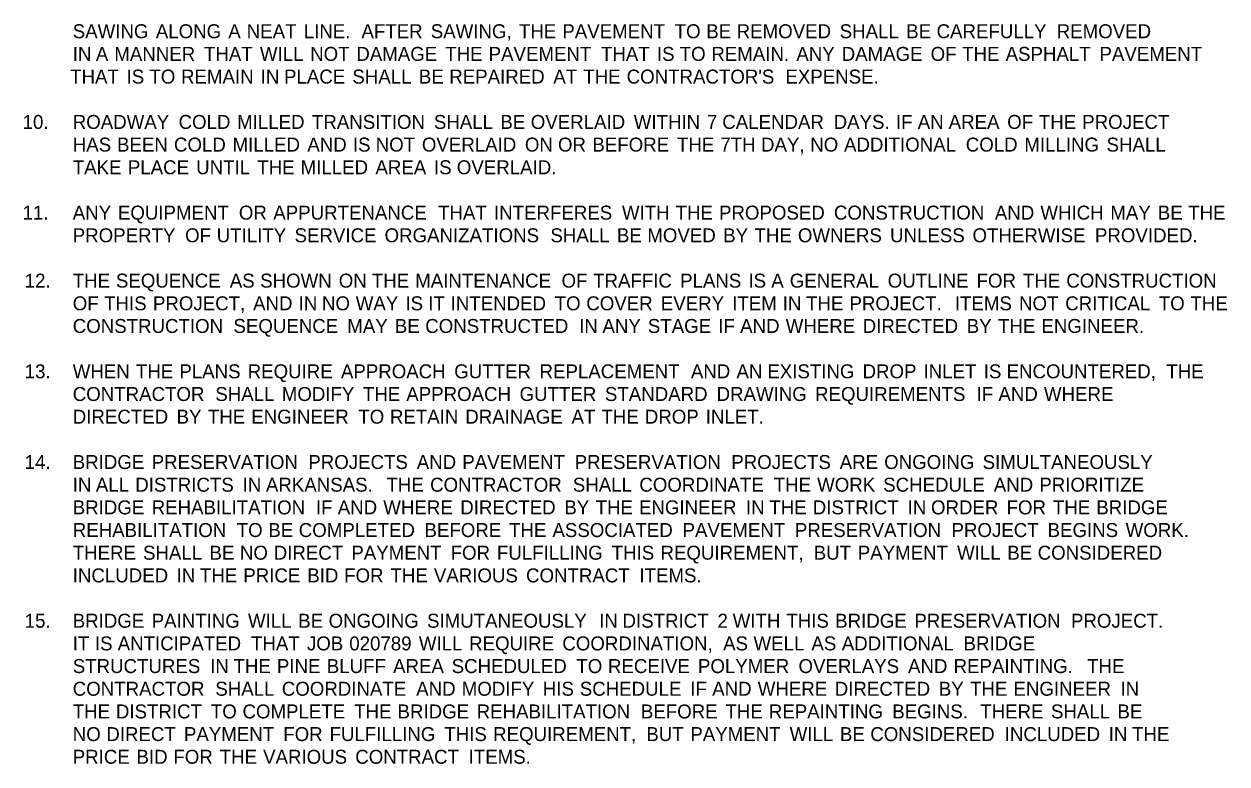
# Model space of a CAD drawing. Extents: x 1930579 to 1932218, y 596452 to 599480.
# Drawn here: x 1930762 to 1931331, y 598694 to 599044 of the extents above; entities that cross this region are included whole.
import ezdxf

# ---------------------------------------------------------------- set-up
doc = ezdxf.new("R2010")
doc.units = 0
doc.layers.add('Default', color=7, linetype='Continuous')

msp = doc.modelspace()

# ---------------------------------------------------------------- texts
at = {"layer": 'Default'}
for s, p in [('SAWING', (1930785.33, 599037.17)), (' ALONG', (1930822.16, 599037.17)), (' SAWING,', (1930952.17, 599037.17)), (' TO', (1931067.5, 599037.17)), (' REMOVED', (1931096.83, 599037.17)), (' SHALL', (1931145.53, 599037.17)), (' CAREFULLY', (1931191.35, 599037.17)), (' REMOVED', (1931248.16, 599037.17)), (' A', (1930856.42, 599037.17)), (' NEAT', (1930865.15, 599037.17)), (' LINE.', (1930892.13, 599037.17)), ('  AFTER', (1930916.94, 599037.17)), (' THE', (1930993.87, 599037.17)), (' PAVEMENT', (1931014.39, 599037.17)), (' BE', (1931082.45, 599037.17)), (' BE', (1931176.98, 599037.17)), ('IN', (1930785.33, 599026.45)), (' A', (1930793.8, 599026.45)), (' MANNER', (1930802.53, 599026.45)), (' THAT', (1930844.93, 599026.45)), (' WILL', (1930871.38, 599026.45)), (' NOT', (1930895.13, 599026.45)), (' DAMAGE', (1930916.98, 599026.45)), (' THE', (1930959.02, 599026.45)), (' PAVEMENT', (1930979.53, 599026.45)), (' THAT', (1931032.64, 599026.45)), (' IS', (1931059.1, 599026.45)), (' TO', (1931069.89, 599026.45)), (' REMAIN.', (1931084.84, 599026.45)), (' ANY', (1931125.03, 599026.45)), (' DAMAGE', (1931146.48, 599026.45)), (' OF', (1931188.52, 599026.45)), (' THE', (1931203.47, 599026.45)), (' ASPHALT', (1931223.98, 599026.45)), (' PAVEMENT', (1931268.39, 599026.45)), ('   THAT', (1930776.75, 599015.72)), (' IS', (1930808.33, 599015.72)), (' TO', (1930819.12, 599015.72)), (' REMAIN', (1930834.08, 599015.72)), (' IN', (1930871.75, 599015.72)), (' PLACE', (1930882.78, 599015.72)), (' SHALL', (1930915.09, 599015.72)), (' BE', (1930946.54, 599015.72)), (' REPAIRED', (1930960.91, 599015.72)), (' AT', (1931010.13, 599015.72)), (' THE', (1931024.29, 599015.72)), (" CONTRACTOR'S", (1931044.8, 599015.72)), (' EXPENSE.', (1931119.86, 599015.72)), ('10.', (1930761.63, 598994.27)), ('ROADWAY', (1930785.33, 598994.27)), (' COLD', (1930832.92, 598994.27)), (' MILLED', (1930860.6, 598994.27)), (' TRANSITION', (1930895.98, 598994.27)), (' SHALL', (1930953.63, 598994.27)), (' BE', (1930985.08, 598994.27)), (' OVERLAID', (1930999.46, 598994.27)), (' WITHIN', (1931048.16, 598994.27)), (' 7', (1931082.75, 598994.27)), (' CALENDAR', (1931090.01, 598994.27)), (' DAYS.', (1931142.67, 598994.27)), (' IF', (1931172.11, 598994.27)), (' AN', (1931182.44, 598994.27)), (' AREA', (1931197.06, 598994.27)), (' OF', (1931224.75, 598994.27)), (' THE', (1931239.7, 598994.27)), (' PROJECT', (1931260.21, 598994.27)), ('HAS', (1930785.33, 598983.55)), (' BEEN', (1930803.82, 598983.55)), (' COLD', (1930830.74, 598983.55)), (' MILLED', (1930858.43, 598983.55)), (' AND', (1930893.8, 598983.55)), (' IS', (1930915.34, 598983.55)), (' NOT', (1930926.13, 598983.55)), (' OVERLAID', (1930947.97, 598983.55)), (' ON', (1930996.68, 598983.55)), (' OR', (1931012.32, 598983.55)), (' BEFORE', (1931028.59, 598983.55)), (' THE', (1931068.58, 598983.55)), (' 7TH', (1931089.09, 598983.55)), (' DAY,', (1931108.33, 598983.55)), (' NO', (1931131.6, 598983.55)), (' ADDITIONAL', (1931147.58, 598983.55)), (' COLD', (1931205.15, 598983.55)), (' MILLING', (1931232.84, 598983.55)), (' SHALL', (1931271.71, 598983.55)), ('TAKE', (1930785.33, 598972.82)), (' PLACE', (1930808.93, 598972.82)), (' UNTIL', (1930841.24, 598972.82)), (' THE', (1930870.12, 598972.82)), (' MILLED', (1930890.63, 598972.82)), (' AREA', (1930926.01, 598972.82)), (' IS', (1930953.7, 598972.82)), (' OVERLAID.', (1930964.49, 598972.82)), ('11.', (1930761.63, 598951.37)), ('ANY', (1930785.33, 598951.37)), (' EQUIPMENT', (1930804.23, 598951.37)), (' OR', (1930861.43, 598951.37)), (' APPURTENANCE', (1930877.7, 598951.37)), (' THAT', (1930955.62, 598951.37)), (' INTERFERES', (1930982.07, 598951.37)), (' WITH', (1931042.57, 598951.37)), (' THE', (1931067.94, 598951.37)), (' PROPOSED', (1931088.46, 598951.37)), (' CONSTRUCTION', (1931142.8, 598951.37)), (' AND', (1931218.9, 598951.37)), (' WHICH', (1931240.44, 598951.37)), (' MAY', (1931273.5, 598951.37)), (' BE', (1931295.97, 598951.37)), (' THE', (1931310.34, 598951.37)), ('PROPERTY', (1930785.33, 598940.65)), (' OF', (1930836, 598940.65)), (' UTILITY', (1930850.95, 598940.65)), (' SERVICE', (1930887.76, 598940.65)), (' ORGANIZATIONS', (1930930.32, 598940.65)), (' SHALL', (1931008.75, 598940.65)), (' BE', (1931040.2, 598940.65)), (' MOVED', (1931054.57, 598940.65)), (' BY', (1931090.46, 598940.65)), (' THE', (1931105.25, 598940.65)), (' OWNERS', (1931125.77, 598940.65)), (' UNLESS', (1931169.35, 598940.65)), (' OTHERWISE', (1931208.33, 598940.65)), (' PROVIDED.', (1931266.24, 598940.65)), ('12.', (1930762.6, 598919.2)), ('THE', (1930785.33, 598919.2)), (' SEQUENCE', (1930803.29, 598919.2)), (' AS', (1930857.12, 598919.2)), (' SHOWN', (1930871.5, 598919.2)), (' ON', (1930908.66, 598919.2)), (' THE', (1930924.3, 598919.2)), (' MAINTENANCE', (1930944.81, 598919.2)), (' OF', (1931014, 598919.2)), (' TRAFFIC', (1931028.95, 598919.2)), (' PLANS', (1931070.08, 598919.2)), (' IS', (1931102.4, 598919.2)), (' A', (1931113.19, 598919.2)), (' GENERAL', (1931121.92, 598919.2)), (' OUTLINE', (1931168.23, 598919.2)), (' FOR', (1931210.26, 598919.2)), (' THE', (1931232.17, 598919.2)), (' CONSTRUCTION', (1931252.68, 598919.2)), ('OF', (1930785.33, 598908.47)), (' THIS', (1930797.72, 598908.47)), (' PROJECT,', (1930820.8, 598908.47)), (' AND', (1930868.15, 598908.47)), (' IN', (1930889.69, 598908.47)), (' NO', (1930900.72, 598908.47)), (' WAY', (1930916.7, 598908.47)), (' IS', (1930940.2, 598908.47)), (' IT', (1930950.99, 598908.47)), (' INTENDED', (1930961.56, 598908.47)), (' TO', (1931010.76, 598908.47)), (' COVER', (1931025.72, 598908.47)), (' EVERY', (1931060.95, 598908.47)), (' ITEM', (1931094.71, 598908.47)), (' IN', (1931118.61, 598908.47)), (' THE', (1931129.63, 598908.47)), (' PROJECT.', (1931150.15, 598908.47)), ('  ITEMS', (1931197.51, 598908.47)), (' NOT', (1931230.33, 598908.47)), (' CRITICAL', (1931252.17, 598908.47)), (' TO', (1931296.42, 598908.47)), (' THE', (1931311.38, 598908.47)), ('CONSTRUCTION', (1930785.33, 598897.75)), (' SEQUENCE', (1930858.87, 598897.75)), (' MAY', (1930912.7, 598897.75)), (' BE', (1930935.18, 598897.75)), (' CONSTRUCTED', (1930949.55, 598897.75)), (' IN', (1931022.32, 598897.75)), (' ANY', (1931033.35, 598897.75)), (' STAGE', (1931054.81, 598897.75)), (' IF', (1931088.14, 598897.75)), (' AND', (1931098.47, 598897.75)), (' WHERE', (1931120.01, 598897.75)), (' DIRECTED', (1931156.41, 598897.75)), (' BY', (1931205.62, 598897.75)), (' THE', (1931220.41, 598897.75)), (' ENGINEER.', (1931240.92, 598897.75)), ('13.', (1930762.6, 598876.3)), ('WHEN', (1930785.33, 598876.3)), (' THE', (1930812.75, 598876.3)), (' PLANS', (1930833.27, 598876.3)), (' REQUIRE', (1930865.59, 598876.3)), (' APPROACH', (1930909.68, 598876.3)), (' GUTTER', (1930963.26, 598876.3)), (' REPLACEMENT', (1931003.61, 598876.3)), (' AND', (1931075.16, 598876.3)), (' AN', (1931096.71, 598876.3)), (' EXISTING', (1931111.32, 598876.3)), (' DROP', (1931156.35, 598876.3)), (' INLET', (1931185.16, 598876.3)), (' IS', (1931213.66, 598876.3)), (' ENCOUNTERED,', (1931224.45, 598876.3)), (' THE', (1931299.98, 598876.3)), ('CONTRACTOR', (1930785.33, 598865.57)), (' SHALL', (1930850.28, 598865.57)), (' MODIFY', (1930881.73, 598865.57)), (' THE', (1930920.08, 598865.57)), (' APPROACH', (1930940.59, 598865.57)), (' GUTTER', (1930994.17, 598865.57)), (' STANDARD', (1931034.52, 598865.57)), (' DRAWING', (1931087.32, 598865.57)), (' REQUIREMENTS', (1931133.88, 598865.57)), (' IF', (1931210.25, 598865.57)), (' AND', (1931220.59, 598865.57)), (' WHERE', (1931242.13, 598865.57)), ('DIRECTED', (1930785.33, 598854.85)), (' BY', (1930831.98, 598854.85)), (' THE', (1930846.78, 598854.85)), (' ENGINEER', (1930867.29, 598854.85)), (' TO', (1930917.9, 598854.85)), (' RETAIN', (1930932.85, 598854.85)), (' DRAINAGE', (1930968.48, 598854.85)), (' AT', (1931018.72, 598854.85)), (' THE', (1931032.88, 598854.85)), (' DROP', (1931053.39, 598854.85)), (' INLET.', (1931082.2, 598854.85)), ('14.', (1930762.6, 598833.4)), ('BRIDGE', (1930785.33, 598833.4)), (' PRESERVATION', (1930820.2, 598833.4)), (' PROJECTS', (1930894.27, 598833.4)), (' AND', (1930945.54, 598833.4)), (' PAVEMENT', (1930967.08, 598833.4)), (' PRESERVATION', (1931020.2, 598833.4)), (' PROJECTS', (1931094.27, 598833.4)), (' ARE', (1931145.54, 598833.4)), (' ONGOING', (1931166.57, 598833.4)), (' SIMULTANEOUSLY', (1931213.13, 598833.4)), ('IN', (1930785.33, 598822.67)), (' ALL', (1930793.8, 598822.67)), (' DISTRICTS', (1930812.44, 598822.67)), (' IN', (1930863.19, 598822.67)), (' ARKANSAS.', (1930874.22, 598822.67)), ('  THE', (1930928.77, 598822.67)), (' CONTRACTOR', (1930951.84, 598822.67)), (' SHALL', (1931019.35, 598822.67)), (' COORDINATE', (1931050.8, 598822.67)), (' THE', (1931114.35, 598822.67)), (' WORK', (1931134.87, 598822.67)), (' SCHEDULE', (1931166.1, 598822.67)), (' AND', (1931218.39, 598822.67)), (' PRIORITIZE', (1931239.93, 598822.67)), ('BRIDGE', (1930785.33, 598811.95)), (' REHABILITATION', (1930820.2, 598811.95)), (' IF', (1930897.84, 598811.95)), (' AND', (1930908.18, 598811.95)), (' WHERE', (1930929.72, 598811.95)), (' DIRECTED', (1930966.11, 598811.95)), (' BY', (1931015.32, 598811.95)), (' THE', (1931030.12, 598811.95)), (' ENGINEER', (1931050.63, 598811.95)), (' IN', (1931101.24, 598811.95)), (' THE', (1931112.26, 598811.95)), (' DISTRICT', (1931132.78, 598811.95)), (' IN', (1931177.68, 598811.95)), (' ORDER', (1931188.7, 598811.95)), (' FOR', (1931224.44, 598811.95)), (' THE', (1931246.35, 598811.95)), (' BRIDGE', (1931266.86, 598811.95)), ('REHABILITATION', (1930785.33, 598801.22)), (' TO', (1930860.42, 598801.22)), (' BE', (1930875.37, 598801.22)), (' COMPLETED', (1930889.75, 598801.22)), (' BEFORE', (1930949.21, 598801.22)), (' THE', (1930989.2, 598801.22)), (' ASSOCIATED', (1931009.71, 598801.22)), (' PAVEMENT', (1931071.23, 598801.22)), (' PRESERVATION', (1931124.34, 598801.22)), (' PROJECT', (1931198.41, 598801.22)), (' BEGINS', (1931243.83, 598801.22)), (' WORK.', (1931280.76, 598801.22)), ('THERE', (1930785.33, 598790.5)), (' SHALL', (1930816.1, 598790.5)), (' BE', (1930847.55, 598790.5)), (' NO', (1930861.92, 598790.5)), (' DIRECT', (1930877.9, 598790.5)), (' PAYMENT', (1930914.61, 598790.5)), (' FOR', (1930961.57, 598790.5)), (' FULFILLING', (1930983.47, 598790.5)), (' THIS', (1931037.71, 598790.5)), (' REQUIREMENT,', (1931060.8, 598790.5)), (' BUT', (1931133.25, 598790.5)), (' PAYMENT', (1931154.07, 598790.5)), (' WILL', (1931201.03, 598790.5)), (' BE', (1931224.78, 598790.5)), (' CONSIDERED', (1931239.15, 598790.5)), ('INCLUDED', (1930785.33, 598779.77)), (' IN', (1930831.98, 598779.77)), (' THE', (1930843.01, 598779.77)), (' PRICE', (1930863.52, 598779.77)), (' BID', (1930893.78, 598779.77)), (' FOR', (1930911.22, 598779.77)), (' THE', (1930933.12, 598779.77)), (' VARIOUS', (1930953.63, 598779.77)), (' CONTRACT', (1930997.22, 598779.77)), (' ITEMS.', (1931050.83, 598779.77)), ('15.', (1930762.6, 598758.32)), ('BRIDGE', (1930785.33, 598758.32)), (' PAINTING', (1930820.2, 598758.32)), (' WILL', (1930865.74, 598758.32)), (' BE', (1930889.48, 598758.32)), (' ONGOING', (1930903.86, 598758.32)), (' SIMUTANEOUSLY', (1930950.41, 598758.32)), (' IN', (1931031.82, 598758.32)), (' DISTRICT', (1931042.85, 598758.32)), (' 2', (1931087.75, 598758.32)), (' WITH', (1931094.94, 598758.32)), (' THIS', (1931120.32, 598758.32)), (' BRIDGE', (1931143.4, 598758.32)), (' PRESERVATION', (1931180.83, 598758.32)), (' PROJECT.', (1931254.9, 598758.32)), ('IT', (1930785.33, 598747.6)), (' IS', (1930793.34, 598747.6)), (' ANTICIPATED', (1930804.13, 598747.6)), (' THAT', (1930867.18, 598747.6)), (' JOB', (1930893.63, 598747.6)), (' 020789', (1930913.64, 598747.6)), (' WILL', (1930946.55, 598747.6)), (' REQUIRE', (1930970.3, 598747.6)), (' COORDINATION,', (1931014.39, 598747.6)), (' AS', (1931090.42, 598747.6)), (' WELL', (1931104.8, 598747.6)), (' AS', (1931132.14, 598747.6)), (' ADDITIONAL', (1931146.52, 598747.6)), (' BRIDGE', (1931204.1, 598747.6)), ('STRUCTURES', (1930785.33, 598736.87)), (' IN', (1930847.88, 598736.87)), (' THE', (1930858.9, 598736.87)), (' PINE', (1930879.42, 598736.87)), (' BLUFF', (1930903.01, 598736.87)), (' AREA', (1930934.36, 598736.87)), (' SCHEDULED', (1930962.05, 598736.87)), (' TO', (1931021, 598736.87)), (' RECEIVE', (1931035.96, 598736.87)), (' POLYMER', (1931078.51, 598736.87)), (' OVERLAYS', (1931126.05, 598736.87)), (' AND', (1931177.85, 598736.87)), (' REPAINTING.', (1931199.39, 598736.87)), ('  THE', (1931260.07, 598736.87)), ('CONTRACTOR', (1930785.33, 598726.15)), (' SHALL', (1930850.28, 598726.15)), (' COORDINATE', (1930881.73, 598726.15)), (' AND', (1930945.28, 598726.15)), (' MODIFY', (1930966.82, 598726.15)), (' HIS', (1931005.18, 598726.15)), (' SCHEDULE', (1931022.63, 598726.15)), (' IF', (1931074.92, 598726.15)), (' AND', (1931085.25, 598726.15)), (' WHERE', (1931106.79, 598726.15)), (' DIRECTED', (1931143.19, 598726.15)), (' BY', (1931192.4, 598726.15)), (' THE', (1931207.19, 598726.15)), (' ENGINEER', (1931227.7, 598726.15)), (' IN', (1931278.31, 598726.15)), ('THE', (1930785.33, 598715.42)), (' DISTRICT', (1930803.29, 598715.42)), (' TO', (1930848.18, 598715.42)), (' COMPLETE', (1930863.14, 598715.42)), (' THE', (1930915.94, 598715.42)), (' BRIDGE', (1930936.45, 598715.42)), (' REHABILITATION', (1930973.88, 598715.42)), (' BEFORE', (1931051.53, 598715.42)), (' THE', (1931091.52, 598715.42)), (' REPAINTING', (1931112.03, 598715.42)), (' BEGINS.', (1931170.38, 598715.42)), ('  THERE', (1931209.55, 598715.42)), (' SHALL', (1931245.44, 598715.42)), (' BE', (1931276.89, 598715.42)), ('NO', (1930785.33, 598704.7)), (' DIRECT', (1930798.75, 598704.7)), (' PAYMENT', (1930835.46, 598704.7)), (' FOR', (1930882.42, 598704.7)), (' FULFILLING', (1930904.32, 598704.7)), (' THIS', (1930958.56, 598704.7)), (' REQUIREMENT,', (1930981.65, 598704.7)), (' BUT', (1931054.1, 598704.7)), (' PAYMENT', (1931074.92, 598704.7)), (' WILL', (1931121.88, 598704.7)), (' BE', (1931145.63, 598704.7)), (' CONSIDERED', (1931160, 598704.7)), (' INCLUDED', (1931223.56, 598704.7)), (' IN', (1931272.77, 598704.7)), (' THE', (1931283.79, 598704.7)), ('PRICE', (1930785.33, 598693.97)), (' BID', (1930813.03, 598693.97)), (' FOR', (1930830.47, 598693.97)), (' THE', (1930852.37, 598693.97)), (' VARIOUS', (1930872.88, 598693.97)), (' CONTRACT', (1930916.47, 598693.97)), (' ITEMS.', (1930970.08, 598693.97))]:
    msp.add_text(s, height=6.6, dxfattribs=at).set_placement(p)

doc.saveas('drawing.dxf')
